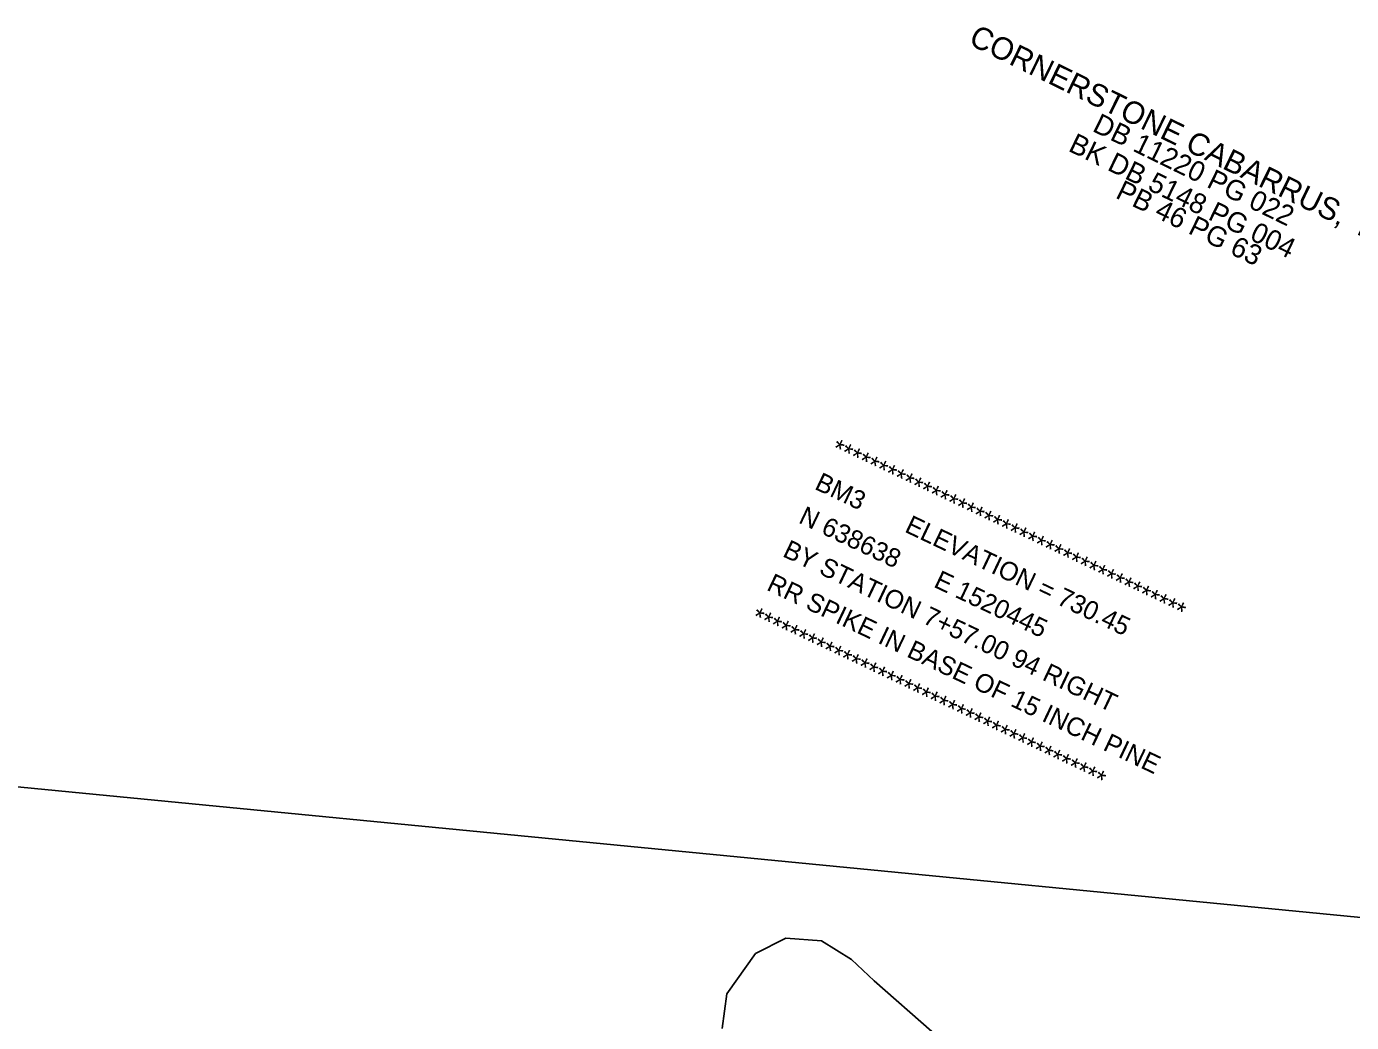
# Model space of a CAD drawing. Extents: x 1516784 to 1522736, y 634838 to 639369.
# Drawn here: x 1520037.3 to 1520333.6, y 638645.9 to 638868.6 of the extents above; entities that cross this region are included whole.
import ezdxf

# ---------------------------------------------------------------- set-up
doc = ezdxf.new("R2010")
doc.units = 0
for name, color, linetype in [('CTL Sheet Text', 7, 'Continuous'), ('Exist Property Deed Book Text', 7, 'Continuous'), ('Exist Property Line', 7, 'Continuous'), ('Exist Property Owner Text', 7, 'Continuous'), ('Exist Vegetation Woods Line', 7, 'Continuous')]:
    doc.layers.add(name, color=color, linetype=linetype)

msp = doc.modelspace()

# ---------------------------------------------------------------- linework, layer by layer
at = {"layer": 'Exist Property Line'}
msp.add_line((1520483.27, 638655.11), (1519625.79, 638738.39), dxfattribs=at)
at = {"layer": 'Exist Vegetation Woods Line'}
msp.add_lwpolyline([(1520239.74, 638643.95), (1520226.87, 638655.27), (1520221.78, 638660.04), (1520215.12, 638664.2), (1520207.09, 638664.76), (1520200.36, 638661.36), (1520193.95, 638652.36), (1520192.89, 638644.59)], dxfattribs=at)

# ---------------------------------------------------------------- texts
at = {"layer": 'CTL Sheet Text'}
for s, p in [('****************************************', (1520216.91, 638772.83)), ('BM3       ELEVATION = 730.45', (1520213.33, 638765.31)), ('N 638638      E 1520445', (1520209.75, 638757.78)), ('BY STATION 7+57.00 94 RIGHT', (1520206.18, 638750.25)), ('RR SPIKE IN BASE OF 15 INCH PINE', (1520202.6, 638742.73)), ('****************************************', (1520199.02, 638735.2))]:
    msp.add_text(s, height=4.1667, rotation=334.5784, dxfattribs=at).set_placement(p)
at = {"layer": 'Exist Property Deed Book Text'}
for s, p in [('DB 11220 PG 022', (1520275.45, 638845.34)), ('BK DB 5148 PG 004', (1520270.06, 638840.92)), ('PB 46 PG 63', (1520280.62, 638830.42))]:
    msp.add_text(s, height=4.5, rotation=333.9377, dxfattribs=at).set_placement(p)
at = {"layer": 'Exist Property Owner Text'}
msp.add_text('CORNERSTONE CABARRUS,  LLC', height=5, rotation=333.9377, dxfattribs=at).set_placement((1520247.76, 638864.75))

doc.saveas('drawing.dxf')
